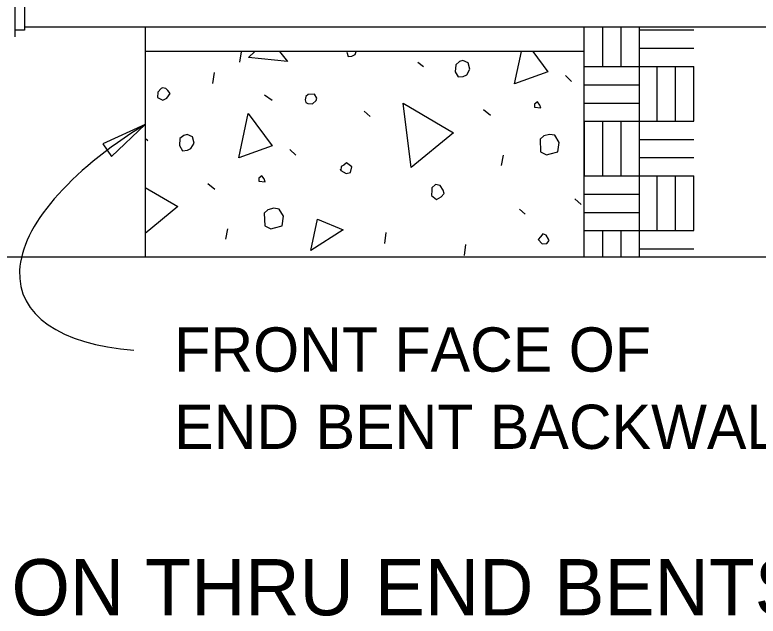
# Model space of a CAD drawing. Extents: x -1660015.2 to -1659984.9, y 2580594.2 to 2580616.7.
# Drawn here: x -1659989.794 to -1659987.255, y 2580606.68 to 2580608.734 of the extents above; entities that cross this region are included whole.
import ezdxf

# ---------------------------------------------------------------- set-up
doc = ezdxf.new("R2010")
doc.units = 0
for name, color, linetype in [('Default', 7, 'Continuous'), ('Miscellaneous', 7, 'Continuous'), ('Miscellaneous3', 7, 'Continuous'), ('PlotBorder_dp', 7, 'Continuous'), ('SheetLines_dp', 7, 'Continuous')]:
    doc.layers.add(name, color=color, linetype=linetype)

msp = doc.modelspace()

# ---------------------------------------------------------------- linework, layer by layer
at = {"layer": 'Default'}
for p, q in [((-1659989.7938, 2580608.8094), (-1659989.7938, 2580608.6595)), ((-1659989.7604, 2580608.7865), (-1659989.7604, 2580608.6823)), ((-1659989.7604, 2580608.6823), (-1659989.7938, 2580608.6823)), ((-1659986.6456, 2580608.6928), (-1659989.7604, 2580608.6928))]:
    msp.add_line(p, q, dxfattribs=at)
at = {"layer": 'Miscellaneous'}
for p, q in [((-1659987.7867, 2580608.6928), (-1659987.7867, 2580608.5578)), ((-1659987.7242, 2580608.6928), (-1659987.7242, 2580608.5578)), ((-1659987.6604, 2580608.5578), (-1659987.6604, 2580608.6928)), ((-1659987.6604, 2580608.6828), (-1659987.4742, 2580608.6828)), ((-1659987.8492, 2580608.6095), (-1659989.3492, 2580608.6095)), ((-1659989.0255, 2580608.5734), (-1659989.0194, 2580608.6087)), ((-1659987.6604, 2580608.6203), (-1659987.4742, 2580608.6203)), ((-1659988.4172, 2580608.5733), (-1659988.3976, 2580608.5579)), ((-1659987.8492, 2580608.5578), (-1659987.6604, 2580608.5578)), ((-1659987.6604, 2580608.1841), (-1659987.6604, 2580608.5578)), ((-1659987.6604, 2580608.5578), (-1659987.4742, 2580608.5578)), ((-1659987.5992, 2580608.3716), (-1659987.5992, 2580608.5578)), ((-1659987.5367, 2580608.3716), (-1659987.5367, 2580608.5578)), ((-1659987.4742, 2580608.3716), (-1659987.4742, 2580608.5578)), ((-1659989.117, 2580608.4997), (-1659989.1116, 2580608.5374)), ((-1659987.9131, 2580608.5272), (-1659987.8922, 2580608.507)), ((-1659987.8492, 2580608.4953), (-1659987.6604, 2580608.4953)), ((-1659988.9411, 2580608.4614), (-1659988.9153, 2580608.4425)), ((-1659987.8492, 2580608.4328), (-1659987.6604, 2580608.4328)), ((-1659988.6, 2580608.4053), (-1659988.5797, 2580608.3875)), ((-1659988.1926, 2580608.411), (-1659988.1692, 2580608.3913)), ((-1659987.8492, 2580608.3716), (-1659987.4742, 2580608.3716)), ((-1659987.8492, 2580608.3716), (-1659987.8492, 2580608.1841)), ((-1659987.7867, 2580608.3716), (-1659987.7867, 2580608.1841)), ((-1659987.7242, 2580608.3716), (-1659987.7242, 2580608.1841)), ((-1659989.3492, 2580608.3133), (-1659989.3394, 2580608.3056)), ((-1659987.6604, 2580608.3091), (-1659987.4742, 2580608.3091)), ((-1659988.8549, 2580608.2749), (-1659988.8339, 2580608.2546)), ((-1659988.1311, 2580608.2204), (-1659988.1251, 2580608.2556)), ((-1659987.6604, 2580608.2466), (-1659987.4742, 2580608.2466)), ((-1659987.8492, 2580608.1841), (-1659987.6604, 2580608.1841)), ((-1659987.6604, 2580608.1841), (-1659987.4742, 2580608.1841)), ((-1659987.6604, 2580607.9066), (-1659987.6604, 2580608.1841)), ((-1659987.5992, 2580607.9978), (-1659987.5992, 2580608.1841)), ((-1659987.5367, 2580607.9978), (-1659987.5367, 2580608.1841)), ((-1659987.4742, 2580607.9978), (-1659987.4742, 2580608.1841)), ((-1659989.1343, 2580608.1586), (-1659989.111, 2580608.139)), ((-1659987.8806, 2580608.1063), (-1659987.8596, 2580608.0861)), ((-1659987.8492, 2580608.1216), (-1659987.6604, 2580608.1216)), ((-1659988.0704, 2580608.071), (-1659988.0501, 2580608.0531)), ((-1659987.8492, 2580608.0591), (-1659987.6604, 2580608.0591)), ((-1659989.0729, 2580607.968), (-1659989.0668, 2580608.0033)), ((-1659987.8492, 2580607.9978), (-1659987.4742, 2580607.9978)), ((-1659987.7867, 2580607.9978), (-1659987.7867, 2580607.9066)), ((-1659987.7242, 2580607.9978), (-1659987.7242, 2580607.9066)), ((-1659988.5305, 2580607.9529), (-1659988.5251, 2580607.9906)), ((-1659988.2581, 2580607.912), (-1659988.2527, 2580607.9497)), ((-1659987.6604, 2580607.9353), (-1659987.4742, 2580607.9353))]:
    msp.add_line(p, q, dxfattribs=at)
for points in [[(-1659988.996, 2580608.5891), (-1659988.9741, 2580608.6095)], [(-1659988.8899, 2580608.6095), (-1659988.863, 2580608.5755), (-1659988.996, 2580608.5891)], [(-1659988.6592, 2580608.6069), (-1659988.6553, 2580608.5924), (-1659988.6426, 2580608.5932), (-1659988.6311, 2580608.5989), (-1659988.6275, 2580608.6095)], [(-1659988.659, 2580608.6095), (-1659988.6592, 2580608.6069)], [(-1659988.0867, 2580608.4989), (-1659988.0632, 2580608.6095)], [(-1659988.0249, 2580608.6095), (-1659987.9734, 2580608.5396), (-1659988.0867, 2580608.4989)], [(-1659988.2879, 2580608.564), (-1659988.2893, 2580608.5403), (-1659988.2793, 2580608.5223), (-1659988.2618, 2580608.5244), (-1659988.2504, 2580608.5301), (-1659988.2397, 2580608.5484), (-1659988.2456, 2580608.5702), (-1659988.2633, 2580608.5784), (-1659988.2754, 2580608.5751), (-1659988.2879, 2580608.564)], [(-1659989.3057, 2580608.4699), (-1659989.306, 2580608.4517), (-1659989.2883, 2580608.4435), (-1659989.2745, 2580608.4498), (-1659989.2632, 2580608.4657), (-1659989.2713, 2580608.4765), (-1659989.278, 2580608.4825), (-1659989.289, 2580608.4847), (-1659989.2938, 2580608.4834), (-1659989.3057, 2580608.4699)], [(-1659988.7994, 2580608.4347), (-1659988.7933, 2580608.4312), (-1659988.7775, 2580608.4302), (-1659988.7649, 2580608.4414), (-1659988.762, 2580608.4499), (-1659988.7707, 2580608.4631), (-1659988.7914, 2580608.4627), (-1659988.7997, 2580608.4553), (-1659988.802, 2580608.4444), (-1659988.7994, 2580608.4347)], [(-1659988.4397, 2580608.2127), (-1659988.4676, 2580608.433), (-1659988.2955, 2580608.3316), (-1659988.4397, 2580608.2127)], [(-1659988.0186, 2580608.4187), (-1659987.9974, 2580608.4167), (-1659988, 2580608.4263), (-1659988.008, 2580608.4371), (-1659988.0188, 2580608.429), (-1659988.0186, 2580608.4187)], [(-1659989.0285, 2580608.2465), (-1659988.9964, 2580608.3974), (-1659988.9152, 2580608.2872), (-1659989.0285, 2580608.2465)], [(-1659989.2297, 2580608.3116), (-1659989.2311, 2580608.288), (-1659989.2211, 2580608.2699), (-1659989.2036, 2580608.2721), (-1659989.1921, 2580608.2777), (-1659989.1815, 2580608.2961), (-1659989.1873, 2580608.3178), (-1659989.2051, 2580608.326), (-1659989.2171, 2580608.3228), (-1659989.2297, 2580608.3116)], [(-1659987.9998, 2580608.3099), (-1659987.9985, 2580608.2663), (-1659987.9777, 2580608.2563), (-1659987.9656, 2580608.2595), (-1659987.9391, 2580608.2667), (-1659987.9348, 2580608.2989), (-1659987.9491, 2580608.3235), (-1659987.968, 2580608.3262), (-1659987.9873, 2580608.321), (-1659987.9998, 2580608.3099)], [(-1659988.6803, 2580608.2026), (-1659988.6619, 2580608.192), (-1659988.6474, 2580608.1959), (-1659988.6423, 2580608.2154), (-1659988.6613, 2580608.2284), (-1659988.6696, 2580608.221), (-1659988.6787, 2580608.216), (-1659988.6803, 2580608.2026), (-1659988.6815, 2580608.2075)], [(-1659988.9604, 2580608.1664), (-1659988.9392, 2580608.1643), (-1659988.9417, 2580608.174), (-1659988.9498, 2580608.1848), (-1659988.9606, 2580608.1767), (-1659988.9604, 2580608.1664)], [(-1659988.3699, 2580608.1357), (-1659988.3702, 2580608.1175), (-1659988.3535, 2580608.1038), (-1659988.3379, 2580608.1132), (-1659988.3278, 2580608.1237), (-1659988.331, 2580608.1357), (-1659988.3404, 2580608.1513), (-1659988.3568, 2580608.1547), (-1659988.3694, 2580608.1436), (-1659988.3699, 2580608.1357)], [(-1659989.3492, 2580608.1452), (-1659989.2373, 2580608.0793), (-1659989.3492, 2580607.987)], [(-1659988.9416, 2580608.0575), (-1659988.9403, 2580608.0139), (-1659988.9195, 2580608.004), (-1659988.9074, 2580608.0072), (-1659988.8808, 2580608.0143), (-1659988.8765, 2580608.0465), (-1659988.8909, 2580608.0711), (-1659988.9097, 2580608.0739), (-1659988.9291, 2580608.0687), (-1659988.9416, 2580608.0575)], [(-1659988.783, 2580607.9292), (-1659988.7599, 2580608.0363), (-1659988.6726, 2580608.0002), (-1659988.783, 2580607.9292)], [(-1659988.0062, 2580607.9666), (-1659987.992, 2580607.9522), (-1659987.9769, 2580607.9537), (-1659987.9691, 2580607.9635), (-1659987.9704, 2580607.9684), (-1659987.9791, 2580607.9816), (-1659987.9907, 2580607.9862), (-1659987.9985, 2580607.9764), (-1659988.0062, 2580607.9666)]]:
    msp.add_lwpolyline(points, dxfattribs=at)
at = {"layer": 'Miscellaneous3'}
for p, q in [((-1659989.3492, 2580608.6928), (-1659989.3492, 2580607.9066)), ((-1659987.8492, 2580607.9066), (-1659987.8492, 2580608.6928))]:
    msp.add_line(p, q, dxfattribs=at)
at = {"layer": 'SheetLines_dp'}
msp.add_lwpolyline([(-1659989.3492, 2580608.3597), (-1659989.4934, 2580608.2942), (-1659989.4638, 2580608.2504)], close=True, dxfattribs=at)
msp.add_lwpolyline([(-1659986.5682, 2580607.9066), (-1659989.8898, 2580607.9066), (-1659989.8898, 2580607.9841), (-1659989.9235, 2580607.9066), (-1659989.9573, 2580607.8291), (-1659989.9573, 2580607.9066), (-1659994.3703, 2580607.9066)], dxfattribs=at)
msp.add_ellipse((-1659988.7415, 2580608.1474), major_axis=(1.0252, 0.3641), ratio=0.417881, start_param=2.049946, end_param=3.892568, dxfattribs=at)

# ---------------------------------------------------------------- texts
at = {"layer": 'PlotBorder_dp'}
msp.add_text('CONCRETE BOX GIRDER BRIDGE SECTION THRU END BENTS', height=0.192, dxfattribs=at).set_placement((-1659994.8125, 2580606.6832))
at = {"layer": 'SheetLines_dp'}
for s, p in [('FRONT FACE OF', (-1659989.2495, 2580607.5156)), ('END BENT BACKWALL', (-1659989.2495, 2580607.2516))]:
    msp.add_text(s, height=0.1512, dxfattribs=at).set_placement(p)

doc.saveas('drawing.dxf')
